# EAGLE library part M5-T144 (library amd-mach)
AMD MACH SERIES
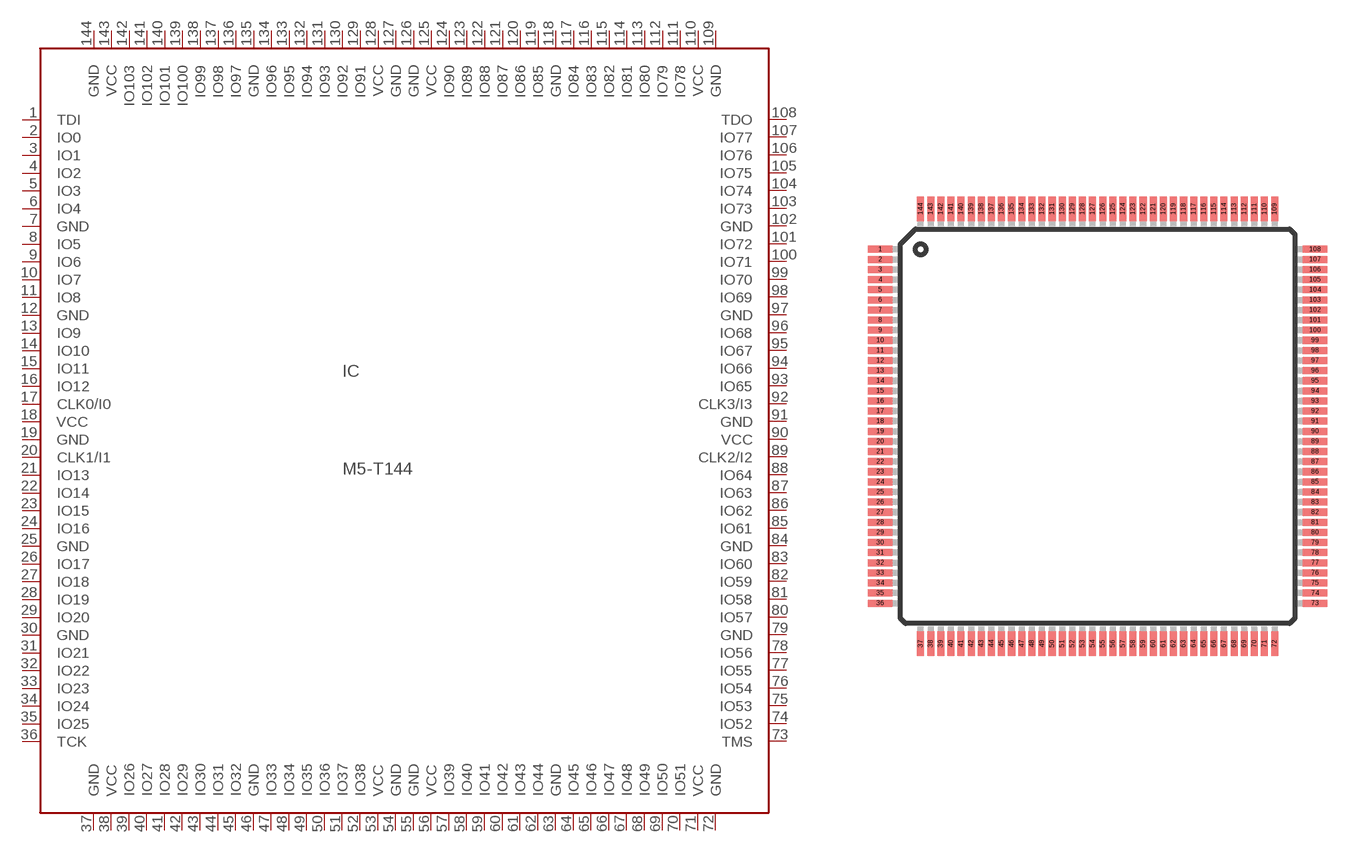
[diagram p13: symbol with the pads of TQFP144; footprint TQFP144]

Designator prefix IC

## M5-T144 (OC_FARNELL: unknown; OC_NEWARK: unknown)  [TQFP144]
1  TDI  in
2  IO0
3  IO1
4  IO2
5  IO3
6  IO4
7  GND  pwr
8  IO5
9  IO6
10  IO7
11  IO8
12  GND  pwr
13  IO9
14  IO10
15  IO11
16  IO12
17  CLK0/I0  in
18  VCC  pwr
19  GND  pwr
20  CLK1/I1  in
21  IO13
22  IO14
23  IO15
24  IO16
25  GND  pwr
26  IO17
27  IO18
28  IO19
29  IO20
30  GND  pwr
31  IO21
32  IO22
33  IO23
34  IO24
35  IO25
36  TCK  in
37  GND  pwr
38  VCC  pwr
39  IO26
40  IO27
41  IO28
42  IO29
43  IO30
44  IO31
45  IO32
46  GND  pwr
47  IO33
48  IO34
49  IO35
50  IO36
51  IO37
52  IO38
53  VCC  pwr
54  GND  pwr
55  GND  pwr
56  VCC  pwr
57  IO39
58  IO40
59  IO41
60  IO42
61  IO43
62  IO44
63  GND  pwr
64  IO45
65  IO46
66  IO47
67  IO48
68  IO49
69  IO50
70  IO51
71  VCC  pwr
72  GND  pwr
73  TMS  in
74  IO52
75  IO53
76  IO54
77  IO55
78  IO56
79  GND  pwr
80  IO57
81  IO58
82  IO59
83  IO60
84  GND  pwr
85  IO61
86  IO62
87  IO63
88  IO64
89  CLK2/I2  in
90  VCC  pwr
91  GND  pwr
92  CLK3/I3  in
93  IO65
94  IO66
95  IO67
96  IO68
97  GND  pwr
98  IO69
99  IO70
100  IO71
101  IO72
102  GND  pwr
103  IO73
104  IO74
105  IO75
106  IO76
107  IO77
108  TDO  out
109  GND  pwr
110  VCC  pwr
111  IO78
112  IO79
113  IO80
114  IO81
115  IO82
116  IO83
117  IO84
118  GND  pwr
119  IO85
120  IO86
121  IO87
122  IO88
123  IO89
124  IO90
125  VCC  pwr
126  GND  pwr
127  GND  pwr
128  VCC  pwr
129  IO91
130  IO92
131  IO93
132  IO94
133  IO95
134  IO96
135  GND  pwr
136  IO97
137  IO98
138  IO99
139  IO100
140  IO101
141  IO102
142  IO103
143  VCC  pwr
144  GND  pwr

## Footprint TQFP144 (pad centres in mm)
THIN QUAD FLAT PACK
smd 1.2 x 0.35: 1 -10.75,8.75; 2 -10.75,8.25; 3 -10.75,7.75; 4 -10.75,7.25; 5 -10.75,6.75; 6 -10.75,6.25; 7 -10.75,5.75; 8 -10.75,5.25; 9 -10.75,4.75; 10 -10.75,4.25; 11 -10.75,3.75; 12 -10.75,3.25; 13 -10.75,2.75; 14 -10.75,2.25; 15 -10.75,1.75; 16 -10.75,1.25; 17 -10.75,0.75; 18 -10.75,0.25; 19 -10.75,-0.25; 20 -10.75,-0.75; 21 -10.75,-1.25; 22 -10.75,-1.75; 23 -10.75,-2.25; 24 -10.75,-2.75; 25 -10.75,-3.25; 26 -10.75,-3.75; 27 -10.75,-4.25; 28 -10.75,-4.75; 29 -10.75,-5.25; 30 -10.75,-5.75; 31 -10.75,-6.25; 32 -10.75,-6.75; 33 -10.75,-7.25; 34 -10.75,-7.75; 35 -10.75,-8.25; 36 -10.75,-8.75; 73 10.75,-8.75; 74 10.75,-8.25; 75 10.75,-7.75; 76 10.75,-7.25; 77 10.75,-6.75; 78 10.75,-6.25; 79 10.75,-5.75; 80 10.75,-5.25; 81 10.75,-4.75; 82 10.75,-4.25; 83 10.75,-3.75; 84 10.75,-3.25; 85 10.75,-2.75; 86 10.75,-2.25; 87 10.75,-1.75; 88 10.75,-1.25; 89 10.75,-0.75; 90 10.75,-0.25; 91 10.75,0.25; 92 10.75,0.75; 93 10.75,1.25; 94 10.75,1.75; 95 10.75,2.25; 96 10.75,2.75; 97 10.75,3.25; 98 10.75,3.75; 99 10.75,4.25; 100 10.75,4.75; 101 10.75,5.25; 102 10.75,5.75; 103 10.75,6.25; 104 10.75,6.75; 105 10.75,7.25; 106 10.75,7.75; 107 10.75,8.25; 108 10.75,8.75
smd 0.35 x 1.2: 37 -8.75,-10.75; 38 -8.25,-10.75; 39 -7.75,-10.75; 40 -7.25,-10.75; 41 -6.75,-10.75; 42 -6.25,-10.75; 43 -5.75,-10.75; 44 -5.25,-10.75; 45 -4.75,-10.75; 46 -4.25,-10.75; 47 -3.75,-10.75; 48 -3.25,-10.75; 49 -2.75,-10.75; 50 -2.25,-10.75; 51 -1.75,-10.75; 52 -1.25,-10.75; 53 -0.75,-10.75; 54 -0.25,-10.75; 55 0.25,-10.75; 56 0.75,-10.75; 57 1.25,-10.75; 58 1.75,-10.75; 59 2.25,-10.75; 60 2.75,-10.75; 61 3.25,-10.75; 62 3.75,-10.75; 63 4.25,-10.75; 64 4.75,-10.75; 65 5.25,-10.75; 66 5.75,-10.75; 67 6.25,-10.75; 68 6.75,-10.75; 69 7.25,-10.75; 70 7.75,-10.75; 71 8.25,-10.75; 72 8.75,-10.75; 109 8.75,10.75; 110 8.25,10.75; 111 7.75,10.75; 112 7.25,10.75; 113 6.75,10.75; 114 6.25,10.75; 115 5.75,10.75; 116 5.25,10.75; 117 4.75,10.75; 118 4.25,10.75; 119 3.75,10.75; 120 3.25,10.75; 121 2.75,10.75; 122 2.25,10.75; 123 1.75,10.75; 124 1.25,10.75; 125 0.75,10.75; 126 0.25,10.75; 127 -0.25,10.75; 128 -0.75,10.75; 129 -1.25,10.75; 130 -1.75,10.75; 131 -2.25,10.75; 132 -2.75,10.75; 133 -3.25,10.75; 134 -3.75,10.75; 135 -4.25,10.75; 136 -4.75,10.75; 137 -5.25,10.75; 138 -5.75,10.75; 139 -6.25,10.75; 140 -6.75,10.75; 141 -7.25,10.75; 142 -7.75,10.75; 143 -8.25,10.75; 144 -8.75,10.75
